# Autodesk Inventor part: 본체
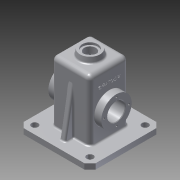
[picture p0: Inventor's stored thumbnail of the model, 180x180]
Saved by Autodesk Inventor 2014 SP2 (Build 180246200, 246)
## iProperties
Created: 2016-02
Part Number: 본체
Material: 알루미늄 6061
Document SubType Name: Modeling
Designer: apexhp001
Density: 2.71 g/cm^3
Appearance: 알루미늄 - 평지
Mass: 932.331 g
Surface Area: 1045.37 cm^2
Volume: 344.034 cm^3
Author: apexhp001
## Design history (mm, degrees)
sketch "스케치1"
  geometry: L1 (-35, 35)-(35, 35); L2 (35, 35)-(35, -35); L3 (35, -35)-(-35, -35); L4 (-35, -35)-(-35, 35); L5 (-35, 35)-(35, -35); L6 (35, 35)-(-35, -35); 1 further point
  constraints: 12 end point, 2 midpoint, 2 parallel, 1 horizontal, 1 perpendicular
  dimensions: "d0" = 70 distance of L1.start L1.end; "d1" = 70 distance of L1.end L2.end
extrude "돌출1" new body sketch "스케치1" distance "d2" = 120; taper "d3" = 0 deg
fillet "모깎기1" dims "d4" = 8
feature "쉘1" dims "d5" = 5
sketch "스케치2"
  geometry: L1 (27, 35)-(-27, 35) reference; L2 (-35, 27)-(-35, -27) reference; L3 (-27, -35)-(27, -35) reference; L4 (35, -27)-(35, 27) reference; L5 (-65, 65)-(65, 65); L6 (65, 65)-(65, -65); L7 (65, -65)-(-65, -65); L8 (-65, -65)-(-65, 65); L9 (-65, 65)-(65, -65); L10 (65, 65)-(-65, -65); A1 r 8 centre (27, 27) between (35, 27) and (27, 35) reference; A2 r 8 centre (-27, 27) between (-27, 35) and (-35, 27) reference; A3 r 8 centre (-27, -27) between (-35, -27) and (-27, -35) reference; A4 r 8 centre (27, -27) between (27, -35) and (35, -27) reference; 1 further point
  constraints: 12 end point, 2 midpoint, 2 parallel, 1 horizontal, 1 perpendicular
  dimensions: "d6" = 130 distance of L5.start L5.end; "d7" = 130 distance of L5.end L6.end
extrude "돌출2" join sketch "스케치2" distance "d8" = 10; taper "d9" = 0 deg
sketch "스케치3"
  geometry: L1 (30, 0)-(30, 112) reference; L2 (48, 55)-(0, 55); L3 (23, 75.5)-(30, 82.5); L4 (30, 82.5)-(48, 82.5); L5 (48, 82.5)-(48, 55); L6 (23, 75.5)-(23, 55); L7 (35, 10)-(35, 112) reference; 1 further point
  constraints: 10 end point, 3 perpendicular, 2 point on line, 1 parallel, 1 vertical alignment
  dimensions: "d10" = 55 distance of point (0, 0) L2.end; "d11" = 135 deg angle of L1 L3; "d13" = 7 distance between parallel lines of L6 L1; "d14" = 13 distance from line of L7 L4.end; "d15" = 55 diameter of L4 L2
revolve "회전1" sketch "스케치3" stored, may be unused: angle "d16" = 90 deg
sketch "스케치4"
  geometry: C1 r 27.5 at (0, 0) reference; C2 r 16 at (0, 0); 1 further point
  constraints: 1 centre point, 1 coincident
  dimensions: "d17" = 32 diameter of C2
extrude "돌출3" cut sketch "스케치4" stored distance "d18" = 10; taper "d19" = 0 deg
sketch "스케치5"
  geometry: C1 r 16 at (0, 0) reference; 2 further points
  constraints: 1 horizontal alignment
  dimensions: "d20" = 22.5 distance of C1.centre point (-22.5, 0)
hole "구멍1" sketch "스케치5" at (-22.5, 0) diameter "d21" = 3.242; stored, may be unused: countersink angle "d25" = 90 deg, drill point angle "d27" = 118 deg; dims "d22" = 8, "d23" = 4, "d24" = 2, "d26" = 10
sketch "스케치6"
  geometry: C1 r 20 at (0, 0); 1 further point
  constraints: 1 centre point, 1 coincident
  dimensions: "d31" = 40 diameter of C1
extrude "돌출4" join sketch "스케치6" distance "d32" = 10; taper "d33" = -10 deg
hole "구멍2" diameter "d36" = 21; stored, may be unused: countersink angle "d40" = 90 deg, drill point angle "d42" = 118 deg; dims "d34" = 10, "d35" = 10, "d37" = 8, "d38" = 28, "d39" = 4, "d41" = 10
sketch "스케치7"
  geometry: L1 (-35, 10)-(-35, 112) reference; L2 (65, 10)-(-65, 10) reference; L3 (35, 112)-(35, 10) reference; L4 (50, 10)-(35, 95.069); L5 (-50, 10)-(-35, 95.069); L6 (65, 0)-(65, 10) reference; 1 further point
  constraints: 4 end point, 4 point on line, 1 equal length
  dimensions: "d43" = 15 distance of L4.start L2.start; "d44" = 10 deg angle of L6 L4; "d45" = 15 distance of L5.start L2.end
extrude "돌출5" join sketch "스케치7" stored distance "d46" = 10; taper "d47" = 0 deg
sketch "스케치8"
  geometry: L1 (-50, 50)-(50, 50); L2 (50, 50)-(50, -50); L3 (50, -50)-(-50, -50); L4 (-50, -50)-(-50, 50); L5 (-50, 50)-(50, -50); L6 (50, 50)-(-50, -50); 1 further point
  constraints: 12 end point, 2 midpoint, 2 parallel, 1 horizontal, 1 perpendicular
  dimensions: "d48" = 100 distance of L1.start L1.end; "d49" = 100 distance of L1.end L2.end
hole "구멍3" sketch "스케치8" at (-50, -50), (50, -50), (50, 50), (-50, 50) diameter "d50" = 12; stored, may be unused: countersink angle "d54" = 90 deg, drill point angle "d56" = 118 deg; dims "d51" = 8, "d52" = 28, "d53" = 4, "d55" = 10
chamfer "모따기1" distance "d57" = 10; stored, may be unused: second distance "d58" = 2, angle "d59" = 45 deg
sketch "스케치9"
  geometry: L1 (-18, 8.763)-(-18, 45.237) reference; L2 (102, 62)-(0, 62) reference; 2 further points
  constraints: 1 other
  dimensions: "d60" = 35 distance from line of point (17, 27) L1; "d61" = 35 distance from line of point (17, 27) L2
feature "엠보싱1" sketch "스케치9" dims "d0" = 70, "d1" = 70, "d62" = 0.5, "d63" = 0
chamfer "모따기2" distance "d64" = 1; stored, may be unused: second distance "d65" = 2, angle "d66" = 45 deg
fillet "모깎기2" dims "d67" = 3
fillet "모깎기3" dims "d68" = 3
fillet "모깎기4" dims "d69" = 0.5
fillet "모깎기5" dims "d70" = 3
node "솔리드1"
mirror "대칭1"
pattern_circular "원형 패턴1" dims angle "d29" = 360 deg
mirror "대칭2"
